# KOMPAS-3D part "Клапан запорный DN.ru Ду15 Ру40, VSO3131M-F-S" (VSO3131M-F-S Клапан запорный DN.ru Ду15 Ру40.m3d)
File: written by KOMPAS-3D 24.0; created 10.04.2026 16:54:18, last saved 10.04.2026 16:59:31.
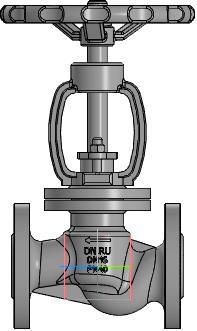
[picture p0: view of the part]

Document properties: Автор: R2D2; Полное имя файла: E:\Работа\Зайцев\VSO3131M-F-S Клапан запорный DN.ru Ду15-100 Ру40\DN15\исходные материалы\VSO3131M-F-S Клапан запорный DN.ru Ду15 Ру40.m3d

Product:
- Part/product: Клапан запорный DN.ru Ду15 Ру40  | designation VSO3131M-F-S
    Масса: 3.77
    Раздел спецификации: Прочие изделия
    Примечание: D090-02137

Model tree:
1. Операция без истории:1
2. Элемент выдавливания:1  (with: Грань.Операция без истории:1)
     Расстояние 1 = 13.25; Расстояние 2 = 19
3. Скругление:1  (with: Грань.Операция без истории:1)
     Радиус = 4
4. Эскиз:1  (with: Грань.Операция без истории:1, Ребро.Операция без истории:1)
5. Элемент выдавливания:2  (with: Грань.Операция без истории:1)
     Расстояние 1 = -60
6. Скругление:2  (with: Грань.Элемент выдавливания:2)
     Радиус = 2
7. Эскиз:2
8. Элемент выдавливания:3
     Расстояние 1 = 5

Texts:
  VSO3131M-F-S
  Угловой размер с обрывом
